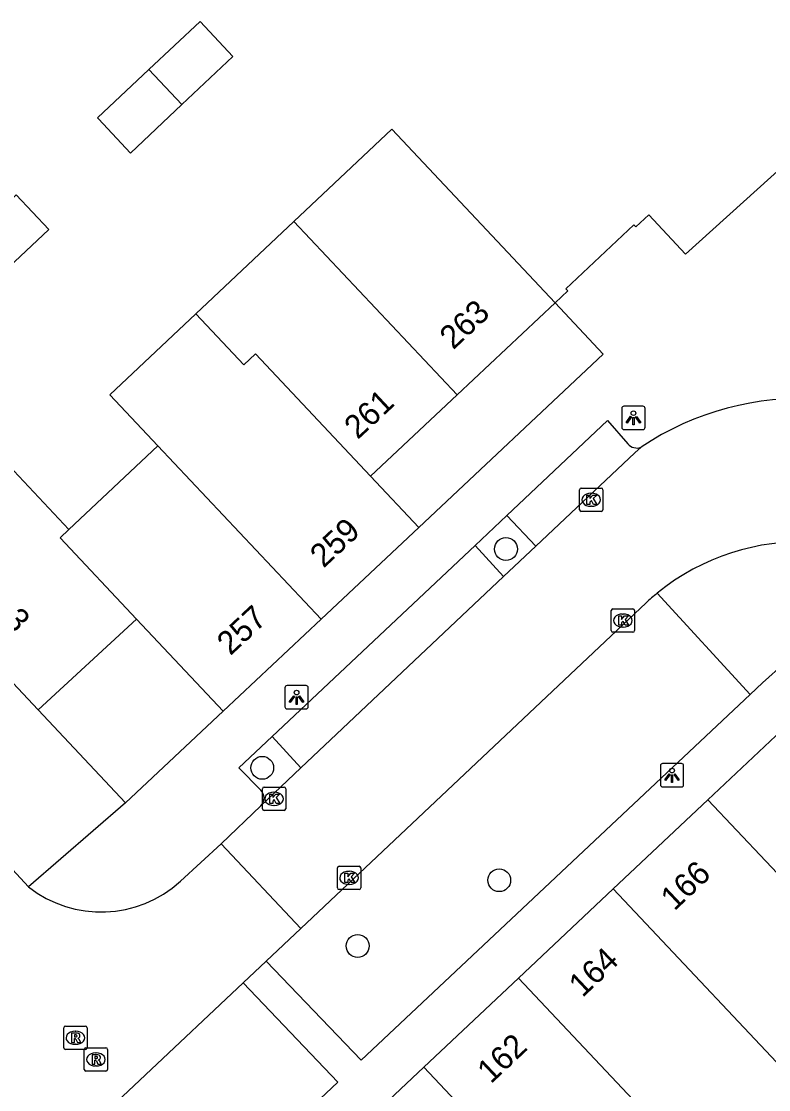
# Model space of a CAD drawing. Extents: x 162542 to 163144, y 380786 to 381511.
# Drawn here: x 162832.73 to 162864.72, y 381396.22 to 381441.97 of the extents above; entities that cross this region are included whole.
import ezdxf

# ---------------------------------------------------------------- set-up
doc = ezdxf.new("R2010")
doc.units = 0
for name, color, linetype in [('IMGEO_Boom', 7, 'Continuous'), ('IMGEO_Groenvoorziening', 7, 'Continuous'), ('IMGEO_Kolk', 7, 'Continuous'), ('IMGEO_Lichtpunt', 7, 'Continuous'), ('IMGEO_Pand', 7, 'Continuous'), ('IMGEO_Pand_nummerreeks', 7, 'Continuous'), ('IMGEO_Parkeervlak_open', 7, 'Continuous'), ('IMGEO_Rijbaan_lokaal_open', 7, 'Continuous'), ('IMGEO_Rioolput', 7, 'Continuous'), ('IMGEO_Voetpad_open', 7, 'Continuous')]:
    doc.layers.add(name, color=color, linetype=linetype)

msp = doc.modelspace()

# ---------------------------------------------------------------- linework, layer by layer
at = {"layer": 'IMGEO_Boom'}
for centre in [(162853.475, 381419.37), (162843.04, 381410.002), (162853.187, 381405.189), (162847.126, 381402.376)]:
    msp.add_circle(centre, 0.489, dxfattribs=at)
at = {"layer": 'IMGEO_Groenvoorziening'}
msp.add_lwpolyline([(162859.95, 381417.481), (162863.931, 381413.146)], dxfattribs=at)
at = {"layer": 'IMGEO_Kolk'}
for p, q in [((162856.624, 381421.056), (162856.624, 381421.908)), ((162856.699, 381421.982), (162857.551, 381421.982)), ((162857.112, 381421.762), (162857.137, 381421.762)), ((162857.625, 381421.908), (162857.625, 381421.056)), ((162857.135, 381421.202), (162857.11, 381421.202)), ((162857.551, 381420.982), (162856.699, 381420.982)), ((162857.982, 381415.883), (162857.982, 381416.735)), ((162858.057, 381416.809), (162858.909, 381416.809)), ((162858.47, 381416.589), (162858.495, 381416.589)), ((162858.983, 381416.735), (162858.983, 381415.883)), ((162858.909, 381415.809), (162858.057, 381415.809)), ((162858.493, 381416.029), (162858.468, 381416.029)), ((162843.046, 381408.25), (162843.046, 381409.102)), ((162843.121, 381409.176), (162843.973, 381409.176)), ((162843.534, 381408.956), (162843.559, 381408.956)), ((162844.047, 381409.102), (162844.047, 381408.25)), ((162843.557, 381408.396), (162843.532, 381408.396)), ((162843.973, 381408.176), (162843.121, 381408.176)), ((162846.257, 381404.865), (162846.257, 381405.717)), ((162846.332, 381405.791), (162847.184, 381405.791)), ((162847.258, 381405.717), (162847.258, 381404.865)), ((162846.745, 381405.571), (162846.77, 381405.571)), ((162847.184, 381404.791), (162846.332, 381404.791)), ((162846.768, 381405.011), (162846.743, 381405.011))]:
    msp.add_line(p, q, dxfattribs=at)
for points in [[(162856.624, 381421.056), (162856.624, 381421.908)], [(162856.699, 381421.982), (162857.551, 381421.982)], [(162856.945, 381421.682), (162857.068, 381421.682), (162857.068, 381421.531), (162857.198, 381421.682), (162857.362, 381421.682), (162857.216, 381421.531), (162857.369, 381421.282), (162857.217, 381421.282), (162857.132, 381421.446), (162857.068, 381421.379), (162857.068, 381421.282), (162856.945, 381421.282), (162856.945, 381421.682)], [(162857.625, 381421.908), (162857.625, 381421.056)], [(162857.551, 381420.982), (162856.699, 381420.982)], [(162857.982, 381415.883), (162857.982, 381416.735)], [(162858.057, 381416.809), (162858.909, 381416.809)], [(162858.983, 381416.735), (162858.983, 381415.883)], [(162858.303, 381416.509), (162858.426, 381416.509), (162858.426, 381416.358), (162858.556, 381416.509), (162858.72, 381416.509), (162858.574, 381416.358), (162858.727, 381416.109), (162858.575, 381416.109), (162858.49, 381416.273), (162858.426, 381416.206), (162858.426, 381416.109), (162858.303, 381416.109), (162858.303, 381416.509)], [(162858.909, 381415.809), (162858.057, 381415.809)], [(162843.046, 381408.25), (162843.046, 381409.102)], [(162843.121, 381409.176), (162843.973, 381409.176)], [(162843.367, 381408.876), (162843.49, 381408.876), (162843.49, 381408.725), (162843.62, 381408.876), (162843.784, 381408.876), (162843.638, 381408.725), (162843.791, 381408.476), (162843.639, 381408.476), (162843.554, 381408.64), (162843.49, 381408.573), (162843.49, 381408.476), (162843.367, 381408.476), (162843.367, 381408.876)], [(162844.047, 381409.102), (162844.047, 381408.25)], [(162843.973, 381408.176), (162843.121, 381408.176)], [(162846.257, 381404.865), (162846.257, 381405.717)], [(162846.332, 381405.791), (162847.184, 381405.791)], [(162847.258, 381405.717), (162847.258, 381404.865)], [(162846.578, 381405.491), (162846.701, 381405.491), (162846.701, 381405.34), (162846.831, 381405.491), (162846.995, 381405.491), (162846.849, 381405.34), (162847.002, 381405.091), (162846.85, 381405.091), (162846.765, 381405.255), (162846.701, 381405.188), (162846.701, 381405.091), (162846.578, 381405.091), (162846.578, 381405.491)], [(162847.184, 381404.791), (162846.332, 381404.791)]]:
    msp.add_lwpolyline(points, dxfattribs=at)
for centre, start, end in [((162856.701, 381421.906), 91.552, 178.448), ((162856.701, 381421.906), 91.552, 178.448), ((162857.549, 381421.906), 1.552, 88.448), ((162857.549, 381421.906), 1.552, 88.448), ((162856.701, 381421.058), 181.552, 268.448), ((162856.701, 381421.058), 181.552, 268.448), ((162857.549, 381421.058), 271.552, 358.448), ((162857.549, 381421.058), 271.552, 358.448), ((162858.059, 381416.733), 91.552, 178.448), ((162858.059, 381416.733), 91.552, 178.448), ((162858.907, 381416.733), 1.552, 88.448), ((162858.907, 381416.733), 1.552, 88.448), ((162858.059, 381415.885), 181.552, 268.448), ((162858.059, 381415.885), 181.552, 268.448), ((162858.907, 381415.885), 271.552, 358.448), ((162858.907, 381415.885), 271.552, 358.448), ((162843.123, 381409.1), 91.552, 178.448), ((162843.123, 381409.1), 91.552, 178.448), ((162843.971, 381409.1), 1.552, 88.448), ((162843.971, 381409.1), 1.552, 88.448), ((162843.123, 381408.252), 181.552, 268.448), ((162843.123, 381408.252), 181.552, 268.448), ((162843.971, 381408.252), 271.552, 358.448), ((162843.971, 381408.252), 271.552, 358.448), ((162846.334, 381405.715), 91.552, 178.448), ((162846.334, 381405.715), 91.552, 178.448), ((162847.182, 381405.715), 1.552, 88.448), ((162847.182, 381405.715), 1.552, 88.448), ((162846.334, 381404.867), 181.552, 268.448), ((162846.334, 381404.867), 181.552, 268.448), ((162847.182, 381404.867), 271.552, 358.448), ((162847.182, 381404.867), 271.552, 358.448)]:
    msp.add_arc(centre, 0.0765, start, end, dxfattribs=at)
for centre, major_axis, ratio, start_param, end_param in [((162857.111, 381421.482), (-0.387, 0.002), 0.722429, 4.712389, 7.853982), ((162857.136, 381421.482), (-0.39, 0.002), 0.717154, 1.570796, 4.712389), ((162858.469, 381416.309), (-0.387, 0.002), 0.722429, 4.712389, 7.853982), ((162858.494, 381416.309), (-0.39, 0.002), 0.717154, 1.570796, 4.712389), ((162843.533, 381408.676), (-0.387, 0.002), 0.722429, 4.712389, 7.853982), ((162843.558, 381408.676), (-0.39, 0.002), 0.717154, 1.570796, 4.712389), ((162846.744, 381405.291), (-0.387, 0.002), 0.722429, 4.712389, 7.853982), ((162846.769, 381405.291), (-0.39, 0.002), 0.717154, 1.570796, 4.712389)]:
    msp.add_ellipse(centre, major_axis=major_axis, ratio=ratio, start_param=start_param, end_param=end_param, dxfattribs=at)
at = {"layer": 'IMGEO_Lichtpunt'}
for p, q in [((162858.435, 381425.39), (162858.435, 381424.583)), ((162858.435, 381425.39), (162858.435, 381424.583)), ((162859.337, 381425.485), (162858.529, 381425.485)), ((162859.337, 381425.485), (162858.529, 381425.485)), ((162859.431, 381424.583), (162859.431, 381425.39)), ((162859.431, 381424.583), (162859.431, 381425.39)), ((162858.529, 381424.489), (162859.337, 381424.489)), ((162858.529, 381424.489), (162859.337, 381424.489)), ((162844.013, 381413.427), (162844.013, 381412.62)), ((162844.013, 381413.427), (162844.013, 381412.62)), ((162844.915, 381413.522), (162844.107, 381413.522)), ((162844.915, 381413.522), (162844.107, 381413.522)), ((162845.009, 381412.62), (162845.009, 381413.427)), ((162845.009, 381412.62), (162845.009, 381413.427)), ((162844.107, 381412.526), (162844.915, 381412.526)), ((162844.107, 381412.526), (162844.915, 381412.526)), ((162860.989, 381410.182), (162860.181, 381410.182)), ((162860.989, 381410.182), (162860.181, 381410.182)), ((162860.087, 381410.087), (162860.087, 381409.28)), ((162860.087, 381410.087), (162860.087, 381409.28)), ((162861.083, 381409.28), (162861.083, 381410.087)), ((162861.083, 381409.28), (162861.083, 381410.087)), ((162860.181, 381409.186), (162860.989, 381409.186)), ((162860.181, 381409.186), (162860.989, 381409.186))]:
    msp.add_line(p, q, dxfattribs=at)
for points in [[(162858.809, 381425.054), (162858.848, 381425.026), (162858.66, 381424.764), (162858.622, 381424.791), (162858.809, 381425.054)], [(162858.911, 381425.006), (162858.958, 381425.006), (162858.958, 381424.684), (162858.911, 381424.684), (162858.911, 381425.006)], [(162859.021, 381425.026), (162859.059, 381425.053), (162859.246, 381424.791), (162859.207, 381424.763), (162859.021, 381425.026)], [(162844.387, 381413.091), (162844.426, 381413.063), (162844.238, 381412.801), (162844.2, 381412.828), (162844.387, 381413.091)], [(162844.489, 381413.043), (162844.536, 381413.043), (162844.536, 381412.721), (162844.489, 381412.721), (162844.489, 381413.043)], [(162844.599, 381413.063), (162844.637, 381413.09), (162844.824, 381412.828), (162844.785, 381412.8), (162844.599, 381413.063)], [(162860.461, 381409.751), (162860.5, 381409.723), (162860.312, 381409.461), (162860.274, 381409.488), (162860.461, 381409.751)], [(162860.673, 381409.723), (162860.711, 381409.75), (162860.898, 381409.488), (162860.859, 381409.46), (162860.673, 381409.723)], [(162860.563, 381409.703), (162860.61, 381409.703), (162860.61, 381409.381), (162860.563, 381409.381), (162860.563, 381409.703)]]:
    msp.add_lwpolyline(points, dxfattribs=at)
for centre in [(162858.934, 381425.188), (162844.512, 381413.225), (162860.586, 381409.885)]:
    msp.add_circle(centre, 0.0994, dxfattribs=at)
for centre, start, end in [((162858.529, 381425.39), 90, 180), ((162858.529, 381425.39), 90, 180), ((162859.337, 381425.39), 0, 90), ((162859.337, 381425.39), 0, 90), ((162858.529, 381424.583), 180, 270), ((162858.529, 381424.583), 180, 270), ((162859.337, 381424.583), 270, 0), ((162859.337, 381424.583), 270, 360), ((162844.107, 381413.427), 90, 180), ((162844.107, 381413.427), 90, 180), ((162844.915, 381413.427), 0, 90), ((162844.915, 381413.427), 0, 90), ((162844.107, 381412.62), 180, 270), ((162844.107, 381412.62), 180, 270), ((162844.915, 381412.62), 270, 0), ((162844.915, 381412.62), 270, 360), ((162860.181, 381410.087), 90, 180), ((162860.181, 381410.087), 90, 180), ((162860.989, 381410.087), 0, 90), ((162860.989, 381410.087), 0, 90), ((162860.181, 381409.28), 180, 270), ((162860.181, 381409.28), 180, 270), ((162860.989, 381409.28), 270, 0), ((162860.989, 381409.28), 270, 360)]:
    msp.add_arc(centre, 0.0946, start, end, dxfattribs=at)
at = {"layer": 'IMGEO_Pand'}
for points in [[(162838.184, 381439.899), (162840.38, 381441.966), (162841.777, 381440.467), (162839.593, 381438.402)], [(162839.593, 381438.402), (162837.397, 381436.327), (162836.026, 381437.791), (162835.988, 381437.832), (162838.184, 381439.899)], [(162838.184, 381439.899), (162839.593, 381438.402)], [(162844.395, 381433.395), (162848.589, 381437.345), (162855.576, 381429.908)], [(162830.301, 381432.471), (162832.502, 381434.539), (162833.897, 381433.054), (162831.696, 381430.986)], [(162840.201, 381429.444), (162844.395, 381433.395)], [(162844.395, 381433.395), (162851.387, 381425.972)], [(162855.576, 381429.908), (162851.387, 381425.972)], [(162838.571, 381423.793), (162836.517, 381425.974), (162840.201, 381429.444)], [(162847.681, 381422.49), (162842.754, 381427.733), (162842.256, 381427.264), (162840.201, 381429.444)], [(162851.387, 381425.972), (162847.681, 381422.49)], [(162825.281, 381421.185), (162829.818, 381425.46), (162834.766, 381420.208)], [(162834.766, 381420.208), (162838.571, 381423.793)], [(162845.564, 381416.369), (162838.571, 381423.793)], [(162847.681, 381422.49), (162849.743, 381420.296)], [(162833.443, 381412.487), (162825.281, 381421.185)], [(162849.743, 381420.296), (162845.564, 381416.369)], [(162837.657, 381416.374), (162834.388, 381419.852), (162834.766, 381420.208)], [(162837.657, 381416.374), (162833.443, 381412.487)], [(162841.367, 381412.426), (162837.657, 381416.374)], [(162845.564, 381416.369), (162841.367, 381412.426)], [(162858.067, 381404.817), (162862.119, 381408.635)], [(162862.119, 381408.635), (162865.839, 381404.688)], [(162854.016, 381400.999), (162858.067, 381404.817)], [(162858.067, 381404.817), (162866.702, 381395.654)], [(162849.964, 381397.181), (162854.016, 381400.999)], [(162854.016, 381400.999), (162862.661, 381391.825)], [(162849.964, 381397.181), (162852.017, 381395.007)]]:
    msp.add_lwpolyline(points, dxfattribs=at)
at = {"layer": 'IMGEO_Parkeervlak_open'}
for points in [[(162854.76, 381419.497), (162853.506, 381420.802)], [(162852.153, 381419.527), (162853.375, 381418.19)], [(162844.695, 381409.997), (162843.468, 381411.342)]]:
    msp.add_lwpolyline(points, dxfattribs=at)
at = {"layer": 'IMGEO_Rijbaan_lokaal_open'}
for points in [[(162859.262, 381423.731), (162858.994, 381423.494), (162854.76, 381419.497)], [(162854.76, 381419.497), (162853.375, 381418.19)], [(162853.375, 381418.19), (162844.695, 381409.997)], [(162859.479, 381417.072), (162844.688, 381403.117)], [(162844.695, 381409.997), (162842.979, 381408.377)], [(162842.979, 381408.377), (162841.279, 381406.751)], [(162839.538, 381405.146), (162841.279, 381406.751)], [(162841.279, 381406.751), (162844.688, 381403.117)], [(162833.031, 381404.902), (162831.827, 381406.209)], [(162844.688, 381403.117), (162843.205, 381401.72)], [(162843.205, 381401.72), (162842.228, 381400.801)], [(162842.228, 381400.801), (162833.858, 381392.922)]]:
    msp.add_lwpolyline(points, dxfattribs=at)
for centre, radius, start, end in [((162866.14, 381413.478), 12.347, 49.4131, 123.8549), ((162866.131, 381409.892), 9.788, 45.1668, 129.1617), ((162866.172, 381409.84), 9.854, 129.156, 132.7838), ((162836.14, 381408.883), 5.051, 232.0155, 312.2794)]:
    msp.add_arc(centre, radius, start, end, dxfattribs=at)
at = {"layer": 'IMGEO_Rioolput'}
for p, q in [((162834.539, 381398.018), (162834.539, 381398.87)), ((162834.614, 381398.944), (162835.466, 381398.944)), ((162835.54, 381398.87), (162835.54, 381398.018)), ((162835.027, 381398.724), (162835.052, 381398.724)), ((162835.466, 381397.944), (162834.614, 381397.944)), ((162835.05, 381398.164), (162835.025, 381398.164)), ((162835.418, 381397.091), (162835.418, 381397.943)), ((162835.493, 381398.017), (162836.345, 381398.017)), ((162836.419, 381397.943), (162836.419, 381397.091)), ((162835.906, 381397.797), (162835.931, 381397.797)), ((162836.345, 381397.017), (162835.493, 381397.017)), ((162835.929, 381397.237), (162835.904, 381397.237))]:
    msp.add_line(p, q, dxfattribs=at)
for points in [[(162834.539, 381398.018), (162834.539, 381398.87)], [(162834.614, 381398.944), (162835.466, 381398.944)], [(162835.54, 381398.87), (162835.54, 381398.018)], [(162835.128, 381398.642), (162834.876, 381398.644), (162834.876, 381398.244)], [(162834.876, 381398.244), (162835, 381398.244), (162835, 381398.406), (162835.011, 381398.406)], [(162835.054, 381398.563), (162835, 381398.563), (162835, 381398.482)], [(162835, 381398.482), (162835.052, 381398.482)], [(162835.058, 381398.377), (162835.129, 381398.244), (162835.269, 381398.244), (162835.204, 381398.37)], [(162835.466, 381397.944), (162834.614, 381397.944)], [(162835.418, 381397.091), (162835.418, 381397.943)], [(162835.493, 381398.017), (162836.345, 381398.017)], [(162836.419, 381397.943), (162836.419, 381397.091)], [(162836.007, 381397.715), (162835.755, 381397.717), (162835.755, 381397.317)], [(162835.755, 381397.317), (162835.879, 381397.317), (162835.879, 381397.479), (162835.89, 381397.479)], [(162835.933, 381397.636), (162835.879, 381397.636), (162835.879, 381397.555)], [(162835.879, 381397.555), (162835.931, 381397.555)], [(162835.937, 381397.45), (162836.008, 381397.317), (162836.148, 381397.317), (162836.083, 381397.443)], [(162836.345, 381397.017), (162835.493, 381397.017)]]:
    msp.add_lwpolyline(points, dxfattribs=at)
for centre, radius, start, end in [((162834.616, 381398.868), 0.0765, 91.552, 178.448), ((162834.616, 381398.868), 0.0765, 91.552, 178.448), ((162835.464, 381398.868), 0.0765, 1.552, 88.448), ((162835.464, 381398.868), 0.0765, 1.552, 88.448), ((162835.01, 381398.353), 0.0533, 26.0293, 88.6989), ((162835.036, 381398.671), 0.19, 274.7715, 282.9687), ((162835.06, 381398.467), 0.0964, 77.0061, 93.1865), ((162835.074, 381398.524), 0.0378, 276.6634, 79.6772), ((162835.127, 381398.532), 0.109, 350.3612, 89.416), ((162835.125, 381398.532), 0.112, 277.5842, 350.9817), ((162835.109, 381398.317), 0.108, 29.5134, 73.7905), ((162834.616, 381398.02), 0.0765, 181.552, 268.448), ((162834.616, 381398.02), 0.0765, 181.552, 268.448), ((162835.495, 381397.941), 0.0765, 91.552, 178.448), ((162835.495, 381397.941), 0.0765, 91.552, 178.448), ((162835.464, 381398.02), 0.0765, 271.552, 358.448), ((162835.464, 381398.02), 0.0765, 271.552, 358.448), ((162836.343, 381397.941), 0.0765, 1.552, 88.448), ((162836.343, 381397.941), 0.0765, 1.552, 88.448), ((162835.889, 381397.426), 0.0533, 26.0293, 88.6989), ((162835.915, 381397.744), 0.19, 274.7715, 282.9687), ((162835.939, 381397.54), 0.0964, 77.0061, 93.1865), ((162835.953, 381397.597), 0.0378, 276.6634, 79.6772), ((162836.006, 381397.605), 0.109, 350.3612, 89.416), ((162836.004, 381397.605), 0.112, 277.5842, 350.9817), ((162835.988, 381397.39), 0.108, 29.5134, 73.7905), ((162835.495, 381397.093), 0.0765, 181.552, 268.448), ((162835.495, 381397.093), 0.0765, 181.552, 268.448), ((162836.343, 381397.093), 0.0765, 271.552, 358.448), ((162836.343, 381397.093), 0.0765, 271.552, 358.448)]:
    msp.add_arc(centre, radius, start, end, dxfattribs=at)
for centre, major_axis, ratio, start_param, end_param in [((162835.026, 381398.444), (-0.387, 0.002), 0.722429, 4.712389, 7.853982), ((162835.051, 381398.444), (-0.39, 0.002), 0.717154, 1.570796, 4.712389), ((162835.905, 381397.517), (-0.387, 0.002), 0.722429, 4.712389, 7.853982), ((162835.93, 381397.517), (-0.39, 0.002), 0.717154, 1.570796, 4.712389)]:
    msp.add_ellipse(centre, major_axis=major_axis, ratio=ratio, start_param=start_param, end_param=end_param, dxfattribs=at)
at = {"layer": 'IMGEO_Voetpad_open'}
for points in [[(162855.576, 381429.908), (162856.123, 381430.422), (162856.034, 381430.516), (162858.949, 381433.255), (162859.038, 381433.161), (162859.586, 381433.676), (162861.159, 381432.002), (162869.05, 381439.12), (162869.767, 381438.361)], [(162855.576, 381429.908), (162857.637, 381427.714), (162849.743, 381420.296)], [(162853.506, 381420.802), (162857.825, 381424.872), (162858.696, 381423.883)], [(162852.153, 381419.527), (162853.506, 381420.802)], [(162843.468, 381411.342), (162852.153, 381419.527)], [(162874.208, 381415.582), (162870.009, 381411.547), (162866.374, 381415.356), (162864.454, 381413.638), (162863.931, 381413.146)], [(162863.931, 381413.146), (162847.275, 381397.482), (162843.205, 381401.72)], [(162837.186, 381408.498), (162833.443, 381412.487)], [(162862.119, 381408.635), (162866.239, 381412.517), (162869.957, 381408.567)], [(162841.367, 381412.426), (162837.186, 381408.498)], [(162842.979, 381409.05), (162842.04, 381409.997), (162843.468, 381411.342)], [(162837.186, 381408.498), (162833.031, 381404.902)], [(162842.228, 381400.801), (162846.277, 381396.546), (162837.912, 381388.648), (162833.858, 381392.922)], [(162808.765, 381354.3), (162806.738, 381356.451), (162849.964, 381397.181)]]:
    msp.add_lwpolyline(points, dxfattribs=at)
for centre, radius, start, end in [((162859.082, 381424.192), 0.495, 218.6449, 291.2907), ((162842.634, 381408.713), 0.482, 315.7042, 44.2958)]:
    msp.add_arc(centre, radius, start, end, dxfattribs=at)

# ---------------------------------------------------------------- texts
at = {"layer": 'IMGEO_Pand_nummerreeks'}
for s, rotation, p in [('263', 43.0177, (162851.216, 381427.877)), ('261', 43.0177, (162847.128, 381424.036)), ('259', 43.0234, (162845.666, 381418.53)), ('3', 312.9831, (162831.945, 381416.277)), ('257', 43.0119, (162841.678, 381414.783)), ('166', 43.2984, (162860.685, 381403.849)), ('164', 43.3042, (162856.749, 381400.14)), ('162', 43.2984, (162852.83, 381396.447))]:
    msp.add_text(s, height=1, rotation=rotation, dxfattribs=at).set_placement(p)

doc.saveas('drawing.dxf')
